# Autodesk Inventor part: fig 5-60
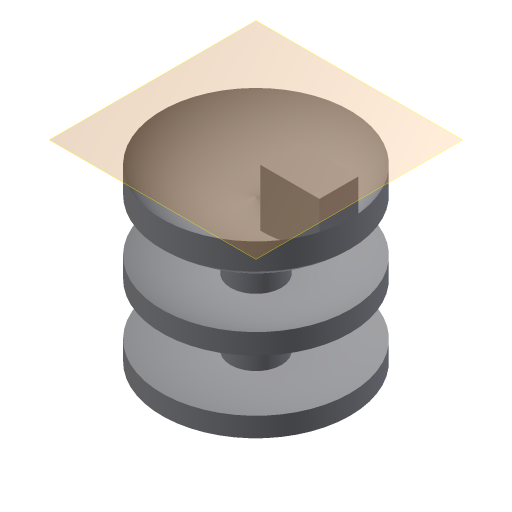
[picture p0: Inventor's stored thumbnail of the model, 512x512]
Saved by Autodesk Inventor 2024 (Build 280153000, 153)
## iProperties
Created: 2004-05
Part Number: fig 5-60
Document SubType Name: Modeling
Designer: CADCIM Technologies
Manufacturer: Standard
Standards Organization: Custom
Density: 1 g/cm^3
Material: Generic
Appearance: Default
Author: CADCIM Technologies
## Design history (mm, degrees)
sketch "Sketch1"
  geometry: L1 (0.098, 22.743)-(0.098, 0.516); L2 (-3.621, 19.305)-(-3.621, 13.061); L3 (-3.621, 10.379)-(-3.621, 3.25); L4 (-3.664, 0.516)-(0.098, 0.516); L5 (-13.694, 4.7)-(-13.694, 1.836); L6 (-13.694, 26.851)-(-13.694, 23.014); L7 (-13.694, 15.335)-(-13.694, 12.343); A1 r 10.546 centre (-4.597, 32.185) between (-13.694, 26.851) and (0.098, 22.743); A2 r 21.828 centre (-4.597, 32.185) between (-13.694, 12.343) and (-3.621, 10.379); A3 r 12.918 centre (-4.597, 32.185) between (-13.694, 23.014) and (-3.621, 19.305); A4 r 19.149 centre (-4.597, 32.185) between (-13.694, 15.335) and (-3.621, 13.061); A5 r 28.952 centre (-4.597, 32.185) between (-13.694, 4.7) and (-3.621, 3.25); A6 r 31.683 centre (-4.597, 32.185) between (-13.694, 1.836) and (-3.664, 0.516)
  constraints: 14 end point, 12 point on circle, 6 centre point, 4 perpendicular, 2 parallel, 1 vertical
revolve "Revolution1" sketch "Sketch1" stored, may be unused: angle "d0" = 90 deg
workplane "Work Plane1"
sketch "Sketch2"
  geometry: L1 (3.408, -2.846)-(12.06, -2.846); L2 (12.06, -2.846)-(12.06, 2.873); L3 (12.06, 2.873)-(3.408, 2.873); L4 (3.408, 2.873)-(3.408, -2.846)
  constraints: 8 end point, 2 parallel, 1 horizontal, 1 perpendicular
extrude "Extrusion3" join sketch "Sketch2" stored distance "d8" = 10; taper "d9" = 0 deg
body "Solid1"
